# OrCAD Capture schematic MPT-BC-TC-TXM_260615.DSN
size A3; title: MPT-BC-ST2(PD Battery Charger); rev: 1; note: 3.TxM
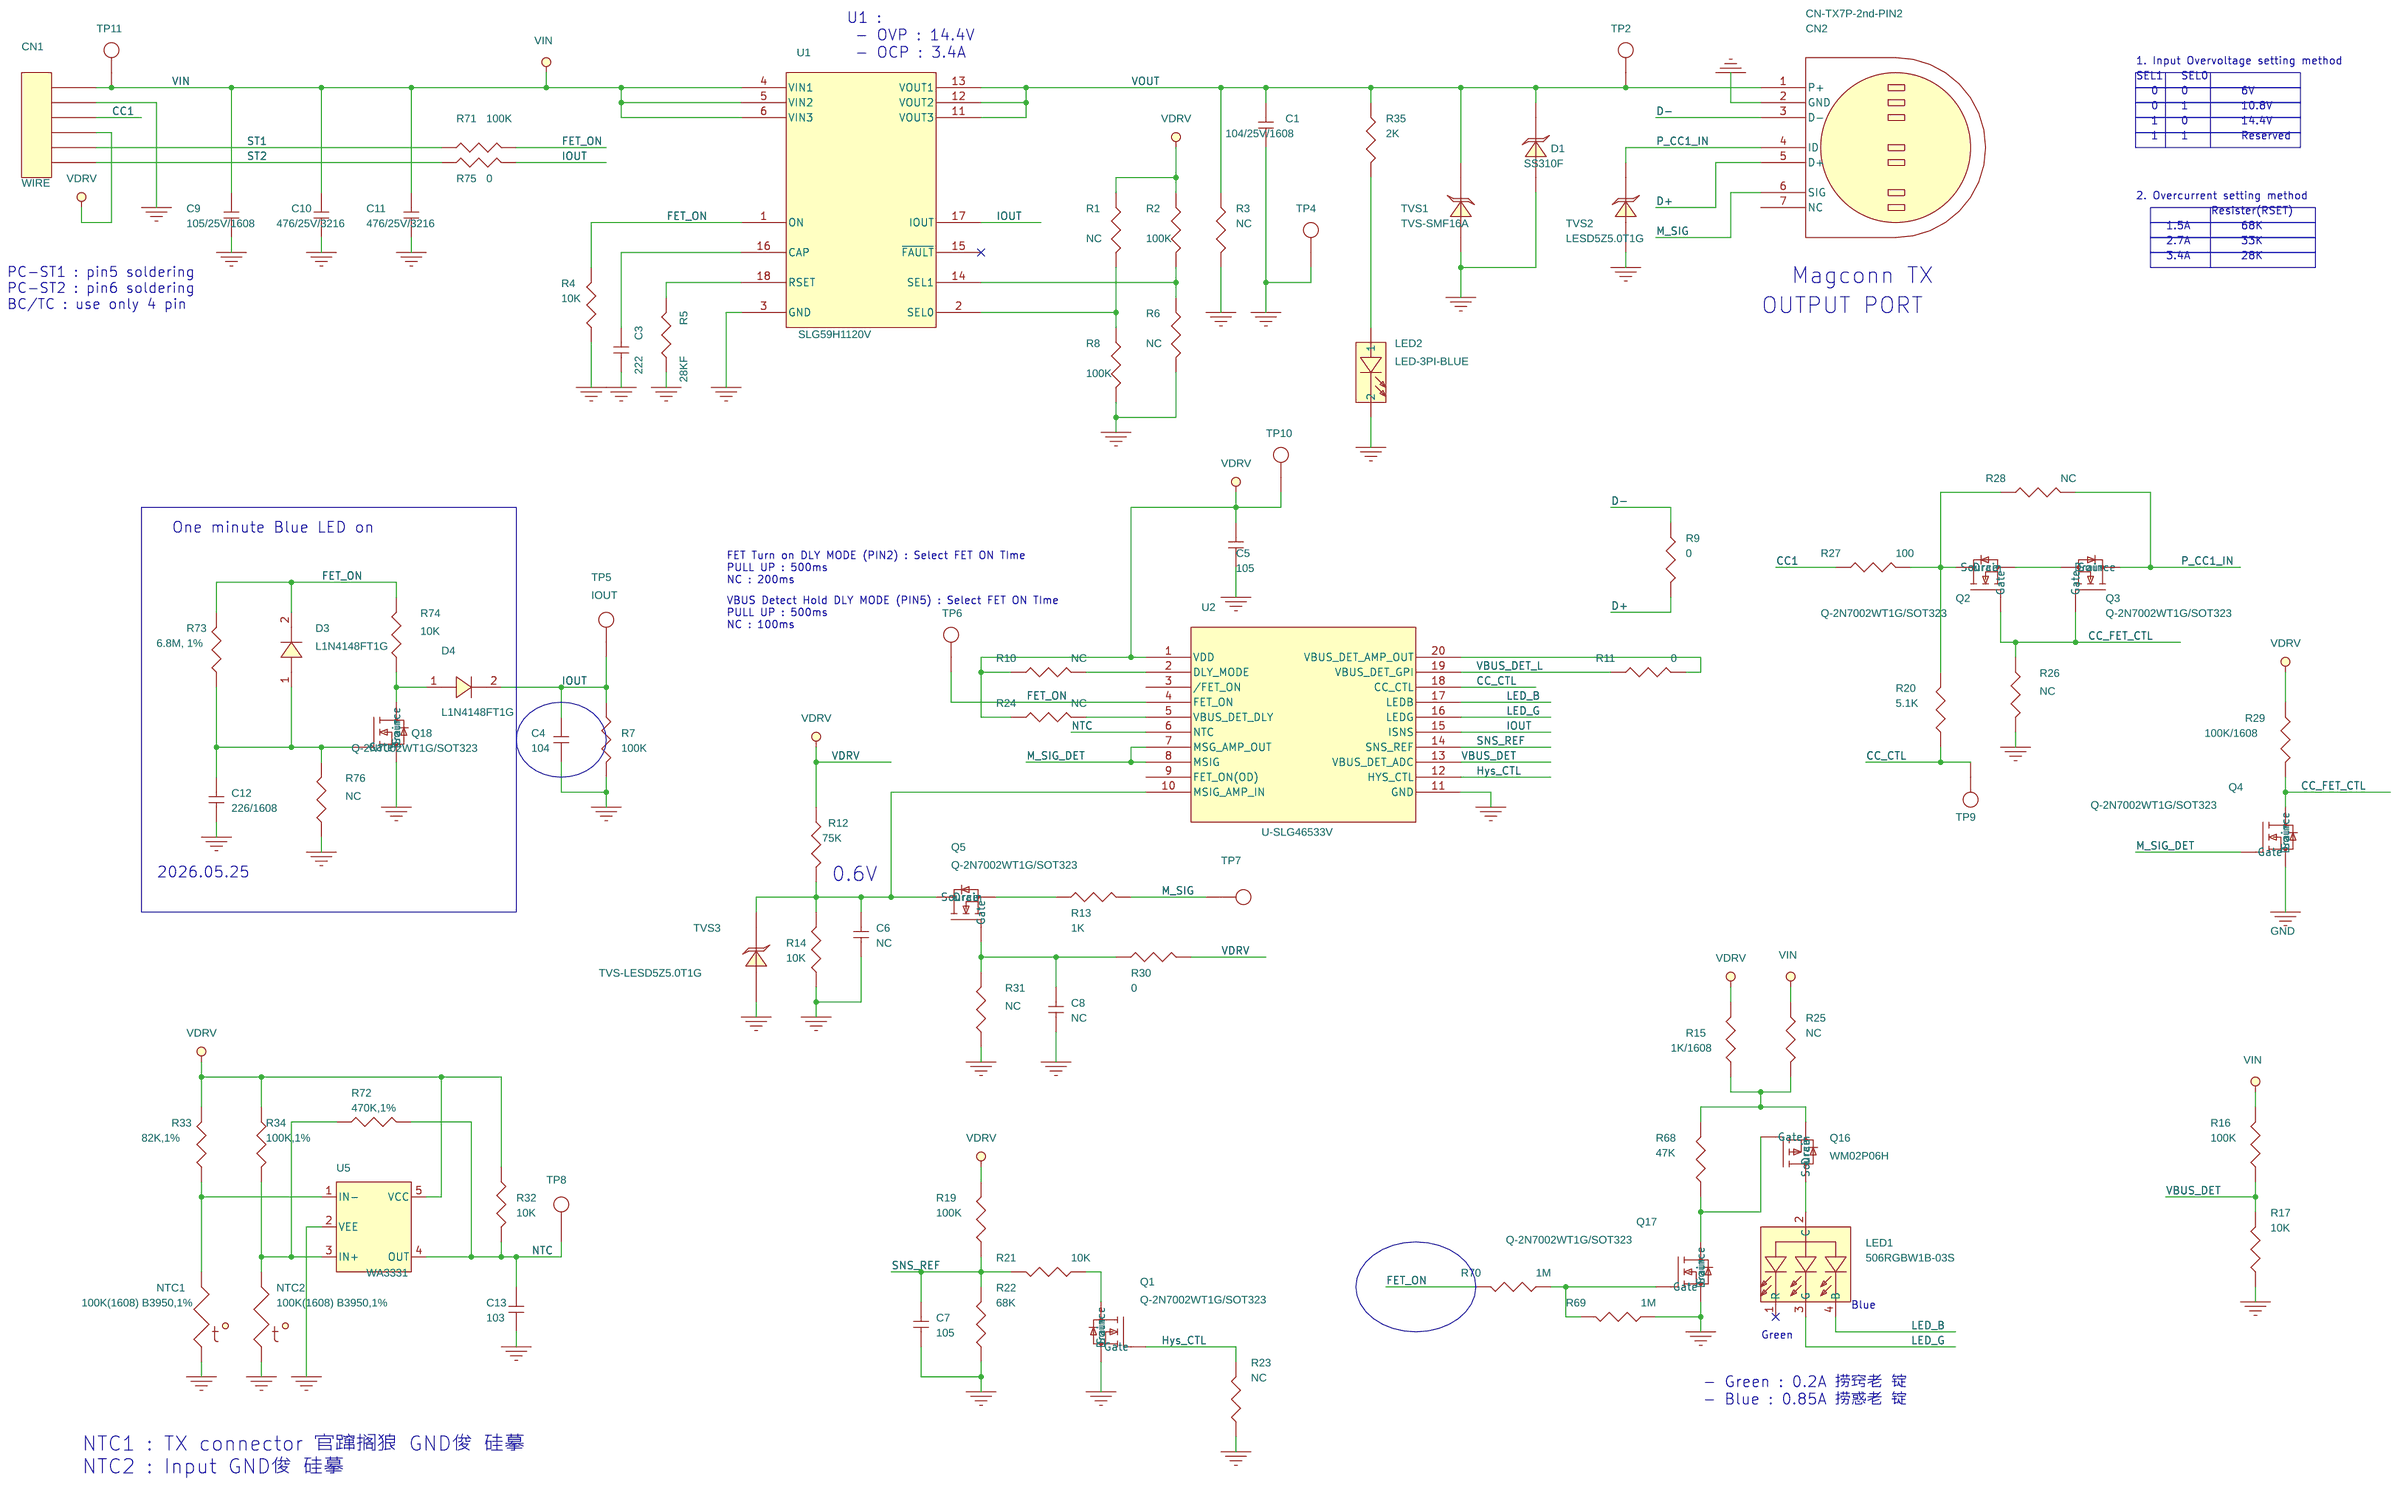
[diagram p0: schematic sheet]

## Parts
C1  104/25V/1608  [C1608T]
C3  222  [C1005T]
C4  104  [C1005T]
C5  105  [C1005T]
C6  NC  [C1005T]
C7  105  [C1005T]
C8  NC  [C1005T]
C9  105/25V/1608  [C1608T]
C10  476/25V/3216  [C3216T]
C11  476/25V/3216  [C3216T]
C12  226/1608  [C1608T]
C13  103  [C1005T]
CN2  CN-TX7P-2nd-PIN2  [CN-TX7P-PIN2-4_3]
D1  SS310F  [SMAT01]
D3  L1N4148FT1G  [SOD523T]
D4  L1N4148FT1G  [SOD523t]
LED1  506RGBW1B-03S  [led_5mm_4p_1P27]
LED2  LED-3PI-BLUE  [led_3pi]
NTC1  100K(1608) B3950,1%  [R1608t]
NTC2  100K(1608) B3950,1%  [R1608T]
Q1  Q-2N7002WT1G/SOT323  [SOT323T]
Q2  Q-2N7002WT1G/SOT323  [SOT323T]
Q3  Q-2N7002WT1G/SOT323  [SOT323T]
Q4  Q-2N7002WT1G/SOT323  [SOT323T]
Q5  Q-2N7002WT1G/SOT323  [SOT323T]
Q16  WM02P06H  [SOT723T]
Q17  Q-2N7002WT1G/SOT323  [SOT323T]
Q18  Q-2N7002WT1G/SOT323  [SOT323T]
R1  NC  [R1005T]
R2  100K  [R1005T]
R3  NC  [R1608T]
R4  10K  [R1005T]
R5  28KF  [R1005T]
R6  NC  [R1005T]
R7  100K  [R1005T]
R8  100K  [R1005T]
R9  0  [R1005T]
R10  NC  [R1005T]
R11  0  [R1005T]
R12  75K  [R1005T]
R13  1K  [R1005T]
R14  10K  [R1005T]
R15  1K/1608  [R1608T]
R16  100K  [R1005T]
R17  10K  [R1005T]
R19  100K  [R1005T]
R20  5.1K  [R1005T]
R21  10K  [R1005T]
R22  68K  [R1005T]
R23  NC  [R1005T]
R24  NC  [R1005T]
R25  NC  [R3216T]
R26  NC  [R1005T]
R27  100  [R1005T]
R28  NC  [R1005T]
R29  100K/1608  [R1608T]
R30  0  [R1005T]
R31  NC  [R1005T]
R32  10K  [R1005T]
R33  82K,1%  [R1005T]
R34  100K,1%  [R1005T]
R35  2K  [R1608T]
R68  47K  [R1005T]
R69  1M  [R1005T]
R70  1M  [R1005T]
R71  100K  [R1005T]
R72  470K,1%  [R1005T]
R73  6.8M, 1%  [R1005T]
R74  10K  [R1005T]
R75  0  [R1005T]
R76  NC  [R1005T]
TP2  VOUT  [TPS1-C0150]
TP4  VOUT  [TPS1-C0150]
TP5  IOUT  [TPS1-C0150]
TP6  VDD33  [TPS1-C0150]
TP7  VDD33  [TPS1-C0150]
TP8  NTC  [TPS1-C0150]
TP9  VBUS  [TPS1-C0150]
TP10  VOUT  [TPS1-C0150]
TP11  VBUS  [TPS1-C0150]
TVS1  TVS-SMF16A  [SOD123FL]
TVS2  LESD5Z5.0T1G  [SOD523T]
TVS3  TVS-LESD5Z5.0T1G  [SOD523T]
U1  SLG59H1120V  [QFN18_0P4T02]
U2  U-SLG46533V  [STQFN20L_0P4T]
U5  WA3331  [SOT235t]
WIRE  CN1

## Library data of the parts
C1 C9-C11 = C-2012_0
C3 C6-C8 C12 = C-1005
C4 C13 = C-2012: 2. Materials_name: CHIP CAP; 4. Manufacture: ANY
C5 = C-1005_0
CN2 = CN-TX7P-V30_0
D1 TVS1 = D-uClamp0501T
D3 D4 = DIODE_2
LED1 = LED-2012_5
LED2 = LED-2012_1
NTC1 NTC2 = NTC
Q1-Q5 Q17 Q18 = Q-2N7002WT1G_SOT323
Q16 = Q-BSS84: 1. ERP_No: 051-FET051-FET0107A0107; 2. Materials_name: FET; 3. Description: MOSFET P-CH 3MOSFET P-CH -20V/0.66A 0.52ohm SOT-7230V 200MA VMT3; 4. Manufacture: WAYON
R1 R2 R6 R8 R13 R30 R31 R73 R74 R76 = R-1005: Unit_Cost: 0.0032
R3 R9-R11 R15 R24 R35 = R-1005
R4 R12 R14 R16 R17 R19-R23 R32-R34 R72 = R-1608
R5 = R-2012
R7 R26-R28 R71 R75 = R-2012: 2. Materials_name: CHIP RES; 4. Manufacture: ANY
R25 = R-3216
R29 = R_3: 2. Materials_name: CHIP RES; 4. Manufacture: ANY; COMPFIXED: NO; COMPGROUP: 0; COMPHEIGHT: 0.025; COMPKEY: NO; COMPLOC: [39.921,88.945]; COMPLOCKED: NO; COMPROT: 90; COMPSIDE: TOP; DECOUPLER: NO; MEMORY: NO
R68-R70 = R_3: 2. Materials_name: CHIP RES; 4. Manufacture: ANY; COMPFIXED: NO; COMPGROUP: 0; COMPHEIGHT: 0.025; COMPKEY: NO; COMPLOC: [39.921,88.945]; COMPLOCKED: NO; COMPROT: 90; COMPSIDE: TOP; DECOUPLER: NO
TP2 TP4-TP11 = TP-testpoint
TVS2 = TVS-LESD5Z12T1G
TVS3 = TVS-LESD5Z5.0T1G
U1 = U-SLG59H1120V
U2 = U-SLG46533V_3
U5 = U-SGM2202_2
WIRE = CON6

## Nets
GND: C1.1 C3.2 C4.1 C5.1 C6.2 C7.2 C8.2 C9.1 C10.1 C11.1 C12.2 C13.1 CN2.2(GND) D1.1 LED2.C(2) NTC1.2 NTC2.2 Q1.2(Source) Q4.2(Source) Q17.2(Source) Q18.2(Source) R3.2 R4.1 R5.1 R6.2 R7.1 R8.2 R14.1 R17.1 R22.1 R23.1 R26.2 R31.1 R69.1 R76.1 TP4.1 TVS1.1 TVS2.1 TVS3.1 U1.3(GND) U2.11(GND) U5.2(VEE) WIRE.2
VBUS_DET: R16.1 R17.2 U2.13(VBUS_DET_ADC)
VBUS_DET_L: R11.1 U2.19(VBUS_DET_GPI)
VIN: C9.2 C10.2 C11.2 R16.2 R25.1 TP11.1 U1.4(VIN1) U1.5(VIN2) U1.6(VIN3) WIRE.1
CC1: R27.1 WIRE.3
CC_CTL: R20.1 TP9.1 U2.18(CC_CTL)
CC_FET_CTL: Q2.1(Gate) Q3.1(Gate) Q4.3(Drain) R26.1 R29.1
D+: CN2.5(D+) R9.2
D-: CN2.3(D-) R9.1
FET_ON: D3.2 R4.2 R70.2 R71.1 R73.2 R74.2 TP6.1 U1.1(ON) U2.4(FET_ON)
Hys_CTL: Q1.1(Gate) R23.2 U2.12(HYS_CTL)
IOUT: C4.2 D4.2 R7.2 R75.1 TP5.1 U1.17(IOUT) U2.15(ISNS)
LED_B: LED1.4(B) U2.17(LEDB)
LED_G: LED1.3(G) U2.16(LEDG)
M_SIG: CN2.6(SIG) R13.2 TP7.1
M_SIG_DET: Q4.1(Gate) U2.7(MSG_AMP_OUT) U2.8(MSIG)
NTC: C13.2 R32.2 R72.1 TP8.1 U2.6(NTC) U5.4(OUT)
P_CC1_IN: CN2.4(ID) Q3.3(Drain) R28.2 TVS2.2
SNS_REF: C7.1 R19.1 R21.2 R22.2 U2.14(SNS_REF)
ST1: R71.2 WIRE.5
ST2: R75.2 WIRE.6
VDRV: C5.2 R1.1 R2.1 R10.1 R12.2 R15.2 R19.2 R24.1 R29.2 R30.2 R32.1 R33.2 R34.2 TP10.1 U2.1(VDD) U5.5(VCC) WIRE.4
VOUT: C1.2 CN2.1(P+) D1.2 R3.1 R35.1 TP2.1 TVS1.2 U1.11(VOUT3) U1.12(VOUT2) U1.13(VOUT1)
N17955140: R10.2 U2.2(DLY_MODE)
N17955821: C6.1 Q5.3(Drain) R12.1 R14.2 TVS3.2 U2.10(MSIG_AMP_IN)
N17957820: R11.2 U2.20(VBUS_DET_AMP_OUT)
N17958213: Q2.3(Drain) R20.2 R27.2 R28.1
N17958535: Q1.3(Drain) R21.1
N17966731: C3.1 U1.16(CAP)
N17966735: R2.2 R6.1 U1.14(SEL1)
N17966737: R5.2 U1.18(RSET)
N17966757: R1.2 R8.1 U1.2(SEL0)
N17974021: R24.2 U2.5(VBUS_DET_DLY)
N17978032: Q2.2(Source) Q3.2(Source)
N17984072: Q5.2(Source) R13.1
N17984105: C8.1 Q5.1(Gate) R30.1 R31.2
N17997895: LED2.A(1) R35.2
N18000198: NTC2.1 R34.1 R72.2 U5.3(IN+)
N18000201: NTC1.1 R33.1 U5.1(IN-)
N18002506: Q16.2(Source) R15.1 R25.2 R68.2
N18002532: Q16.1(Gate) Q17.3(Drain) R68.1
N18002543: LED1.2(C) Q16.3(Drain)
N18002589: Q17.1(Gate) R69.2 R70.1
N18017535: C12.1 D3.1 Q18.1(Gate) R73.1 R76.2
N18017794: D4.1 Q18.3(Drain) R74.1

Not connected (* = marked no-connect by the designer): CN2 7(NC); LED1 1(R)*; U1 15(~{FAULT})*; U2 3(/FET_ON) 9(FET_ON(OD))

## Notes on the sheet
- U1 :
   - OVP : 14.4V
   - OCP : 3.4A
- 1. Input Overvoltage setting method
- SEL1
- SEL0
- 0
- 0
- 6V
- 0
- 1
- 10.8V
- 1
- 0
- 14.4V
- 1
- 1
- Reserved
- 2. Overcurrent setting method
- Resister(RSET)
- 1.5A
- 68K
- 2.7A
- 3.4A
- 28K
- 33K
- PC-ST1 : pin5 soldering
  PC-ST2 : pin6 soldering
  BC/TC : use only 4 pin
- Magconn TX
- OUTPUT PORT
- One minute Blue LED on
- FET Turn on DLY MODE (PIN2) : Select FET ON TIme
  PULL UP : 500ms
  NC : 200ms
- VBUS Detect Hold DLY MODE (PIN5) : Select FET ON TIme
  PULL UP : 500ms
  NC : 100ms
- 2026.05.25
- 0.6V
- Blue
- Green
- - Green : 0.2A 捞窍老 锭
    - Blue : 0.85A 捞惑老 锭
- NTC1 : TX connector 官蹿搁狼 GND俊 硅摹
  NTC2 : Input GND俊 硅摹
